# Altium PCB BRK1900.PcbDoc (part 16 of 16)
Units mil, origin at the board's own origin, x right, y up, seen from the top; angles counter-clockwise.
Board outline 8858.27 x 5905.51 mil, 10 copper layers (L1-TOP, L2-GND, L3-PWR, L4-GND, L5-PWR, L6-PWR, L7-GND, L8-SIG, L9-GND, L10-BOT), stack 48.824 mil thick; 456 components, 571 nets, 2296 pads, 2416 vias.
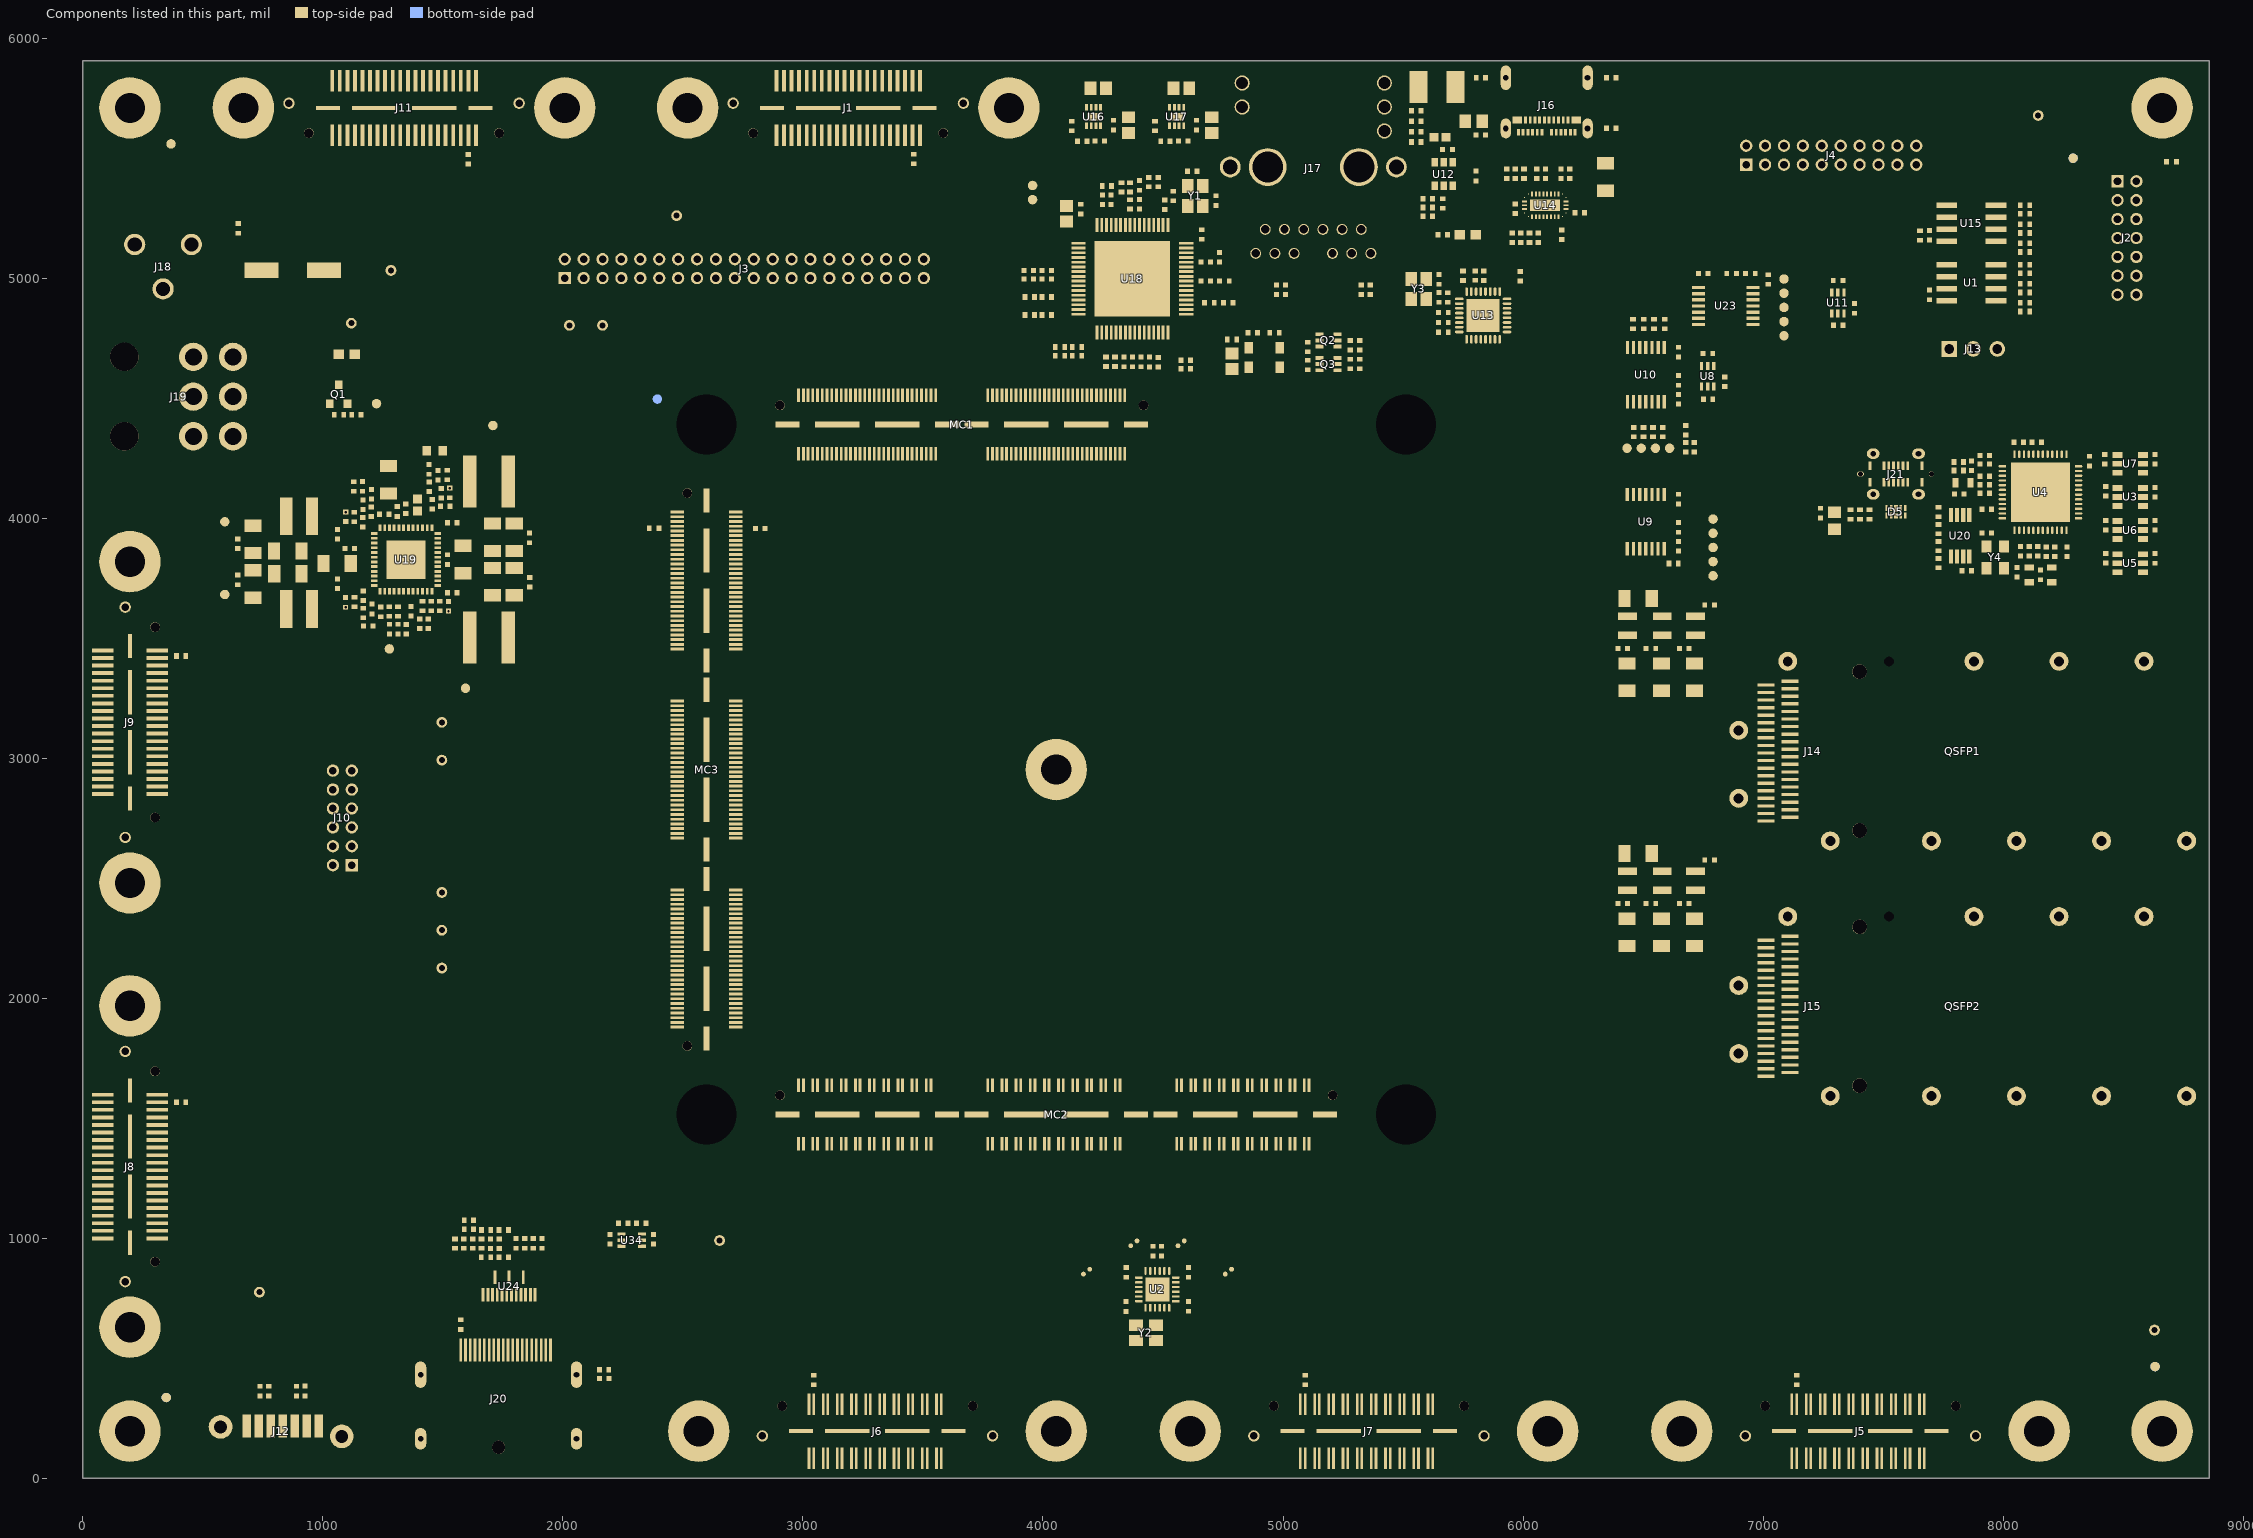
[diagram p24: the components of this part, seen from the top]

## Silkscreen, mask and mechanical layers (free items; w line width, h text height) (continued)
Drill Drawing:
  drawing of 162 lines, arcs and shapes, not listed
  text "DRILL TABLE" at 9511.81,5524.57 h50
  text "Symbol" at 9550.58,5424.22 h47.91
  text "Count" at 9897.89,5424.22 h47.91
  text "Finished Hole Size" at 10343.61,5424.22 h47.91
  text "Slot Length" at 11249.66,5424.22 h47.91
  text "Plated" at 11988.06,5424.22 h47.91
  text "Drill Layer Pair" at 12335.37,5424.22 h47.91
  text "Via/Pad" at 13137.65,5424.22 h47.91
  text "Hole Tolerance (+)" at 13540.83,5424.22 h47.91
  text "Hole Tolerance (-)" at 14438.89,5424.22 h47.91
  text "2420" at 9897.89,5324.41 h39.92
  text "10.00mil (0.254mm)" at 10343.61,5324.41 h39.92
  text "-" at 11249.66,5324.41 h39.92
  text "PTH" at 11988.06,5324.41 h39.92
  text "L1-TOP - L10-BOT" at 12335.37,5324.41 h39.92
  text "(Mixed)" at 13137.65,5324.41 h39.92
  text "3.00mil (0.076mm)" at 13540.83,5324.41 h39.92
  text "3.00mil (0.076mm)" at 14438.89,5324.41 h39.92
  text "1" at 9897.89,5224.6 h39.92
  text "20.47mil (0.520mm)" at 10343.61,5224.6 h39.92
  text "-" at 11249.66,5224.6 h39.92
  text "NPTH" at 11988.06,5224.6 h39.92
  text "L1-TOP - L10-BOT" at 12335.37,5224.6 h39.92
  text "Pad" at 13137.65,5224.6 h39.92
  text "3.00mil (0.076mm)" at 13540.83,5224.6 h39.92
  text "3.00mil (0.076mm)" at 14438.89,5224.6 h39.92
  text "E" at 9528.92,5214.61 h44.36
  text "1" at 9897.89,5124.8 h39.92
  text "20.47mil (0.520mm)" at 10343.61,5124.8 h39.92
  text "28.35mil (0.720mm)" at 11249.66,5124.8 h39.92
  text "NPTH" at 11988.06,5124.8 h39.92
  text "L1-TOP - L10-BOT" at 12335.37,5124.8 h39.92
  text "Pad" at 13137.65,5124.8 h39.92
  text "3.00mil (0.076mm)" at 13540.83,5124.8 h39.92
  text "3.00mil (0.076mm)" at 14438.89,5124.8 h39.92
  text "H" at 9528.92,5114.8 h44.36
  text "4" at 9897.89,5024.99 h39.92
  text "23.62mil (0.600mm)" at 10343.61,5024.99 h39.92
  text "33.47mil (0.850mm)" at 11249.66,5024.99 h39.92
  text "PTH" at 11988.06,5024.99 h39.92
  text "L1-TOP - L10-BOT" at 12335.37,5024.99 h39.92
  text "Pad" at 13137.65,5024.99 h39.92
  text "3.00mil (0.076mm)" at 13540.83,5024.99 h39.92
  text "3.00mil (0.076mm)" at 14438.89,5024.99 h39.92
  text "G" at 9528.92,5015 h44.36
  text "2" at 9897.89,4925.18 h39.92
  text "23.62mil (0.600mm)" at 10343.61,4925.18 h39.92
  text "62.99mil (1.600mm)" at 11249.66,4925.18 h39.92
  text "PTH" at 11988.06,4925.18 h39.92
  text "L1-TOP - L10-BOT" at 12335.37,4925.18 h39.92
  text "Pad" at 13137.65,4925.18 h39.92
  text "3.00mil (0.076mm)" at 13540.83,4925.18 h39.92
  text "3.00mil (0.076mm)" at 14438.89,4925.18 h39.92
  text "2" at 9897.89,4825.37 h39.92
  text "23.62mil (0.600mm)" at 10343.61,4825.37 h39.92
  text "66.93mil (1.700mm)" at 11249.66,4825.37 h39.92
  text "PTH" at 11988.06,4825.37 h39.92
  text "L1-TOP - L10-BOT" at 12335.37,4825.37 h39.92
  text "Pad" at 13137.65,4825.37 h39.92
  text "3.00mil (0.076mm)" at 13540.83,4825.37 h39.92
  text "3.00mil (0.076mm)" at 14438.89,4825.37 h39.92
  text "2" at 9897.89,4725.57 h39.92
  text "23.62mil (0.600mm)" at 10343.61,4725.57 h39.92
  text "82.68mil (2.100mm)" at 11249.66,4725.57 h39.92
  text "PTH" at 11988.06,4725.57 h39.92
  text "L1-TOP - L10-BOT" at 12335.37,4725.57 h39.92
  text "Pad" at 13137.65,4725.57 h39.92
  text "3.00mil (0.076mm)" at 13540.83,4725.57 h39.92
  text "3.00mil (0.076mm)" at 14438.89,4725.57 h39.92
  text "2" at 9897.89,4625.76 h39.92
  text "23.62mil (0.600mm)" at 10343.61,4625.76 h39.92
  text "86.61mil (2.200mm)" at 11249.66,4625.76 h39.92
  text "PTH" at 11988.06,4625.76 h39.92
  text "L1-TOP - L10-BOT" at 12335.37,4625.76 h39.92
  text "Pad" at 13137.65,4625.76 h39.92
  text "3.00mil (0.076mm)" at 13540.83,4625.76 h39.92
  text "3.00mil (0.076mm)" at 14438.89,4625.76 h39.92
  text "14" at 9897.89,4525.95 h39.92
  text "25.00mil (0.635mm)" at 10343.61,4525.95 h39.92
  text "-" at 11249.66,4525.95 h39.92
  text "PTH" at 11988.06,4525.95 h39.92
  text "L1-TOP - L10-BOT" at 12335.37,4525.95 h39.92
  text "Pad" at 13137.65,4525.95 h39.92
  text "3.00mil (0.076mm)" at 13540.83,4525.95 h39.92
  text "3.00mil (0.076mm)" at 14438.89,4525.95 h39.92
  text "14" at 9897.89,4426.15 h39.92
  text "31.50mil (0.800mm)" at 10343.61,4426.15 h39.92
  text "-" at 11249.66,4426.15 h39.92
  text "PTH" at 11988.06,4426.15 h39.92
  text "L1-TOP - L10-BOT" at 12335.37,4426.15 h39.92
  text "Pad" at 13137.65,4426.15 h39.92
  text "3.00mil (0.076mm)" at 13540.83,4426.15 h39.92
  text "3.00mil (0.076mm)" at 14438.89,4426.15 h39.92
  text "86" at 9897.89,4326.34 h39.92
  text "31.50mil (0.800mm)" at 10343.61,4326.34 h39.92
  text "-" at 11249.66,4326.34 h39.92
  text "PTH" at 11988.06,4326.34 h39.92
  text "L1-TOP - L10-BOT" at 12335.37,4326.34 h39.92
  text "Pad" at 13137.65,4326.34 h39.92
  text "3.15mil (0.080mm)" at 13540.83,4326.34 h39.92
  text "3.15mil (0.080mm)" at 14438.89,4326.34 h39.92
  text "C" at 9528.92,4316.35 h44.36
  text "12" at 9897.89,4226.53 h39.92
  text "35.04mil (0.890mm)" at 10343.61,4226.53 h39.92
  text "-" at 11249.66,4226.53 h39.92
  text "PTH" at 11988.06,4226.53 h39.92
  text "L1-TOP - L10-BOT" at 12335.37,4226.53 h39.92
  text "Pad" at 13137.65,4226.53 h39.92
  text "5.00mil (0.127mm)" at 13540.83,4226.53 h39.92
  text "0.00mil (0.000mm)" at 14438.89,4226.53 h39.92
  text "A" at 9528.92,4216.54 h44.36
  text "3" at 9897.89,4126.73 h39.92
  text "40.00mil (1.016mm)" at 10343.61,4126.73 h39.92
  text "-" at 11249.66,4126.73 h39.92
  text "PTH" at 11988.06,4126.73 h39.92
  text "L1-TOP - L10-BOT" at 12335.37,4126.73 h39.92
  text "Pad" at 13137.65,4126.73 h39.92
  text "3.00mil (0.076mm)" at 13540.83,4126.73 h39.92
  text "3.00mil (0.076mm)" at 14438.89,4126.73 h39.92
  text "20" at 9897.89,4026.92 h39.92
  text "40.16mil (1.020mm)" at 10343.61,4026.92 h39.92
  text "-" at 11249.66,4026.92 h39.92
  text "NPTH" at 11988.06,4026.92 h39.92
  text "L1-TOP - L10-BOT" at 12335.37,4026.92 h39.92
  text "Pad" at 13137.65,4026.92 h39.92
  text "3.00mil (0.076mm)" at 13540.83,4026.92 h39.92
  text "3.00mil (0.076mm)" at 14438.89,4026.92 h39.92
  text "2" at 9897.89,3927.11 h39.92
  text "41.34mil (1.050mm)" at 10343.61,3927.11 h39.92
  text "-" at 11249.66,3927.11 h39.92
  text "NPTH" at 11988.06,3927.11 h39.92
  text "L1-TOP - L10-BOT" at 12335.37,3927.11 h39.92
  text "Pad" at 13137.65,3927.11 h39.92
  text "3.00mil (0.076mm)" at 13540.83,3927.11 h39.92
  text "3.00mil (0.076mm)" at 14438.89,3927.11 h39.92
  text "J" at 9528.92,3917.12 h44.36
  text "22" at 9897.89,3827.3 h39.92
  text "41.34mil (1.050mm)" at 10343.61,3827.3 h39.92
  text "-" at 11249.66,3827.3 h39.92
  text "PTH" at 11988.06,3827.3 h39.92
  text "L1-TOP - L10-BOT" at 12335.37,3827.3 h39.92
  text "Pad" at 13137.65,3827.3 h39.92
  text "3.00mil (0.076mm)" at 13540.83,3827.3 h39.92
  text "3.00mil (0.076mm)" at 14438.89,3827.3 h39.92
  text "M" at 9528.92,3817.31 h44.36
  text "5" at 9897.89,3727.5 h39.92
  text "50.00mil (1.270mm)" at 10343.61,3727.5 h39.92
  text "-" at 11249.66,3727.5 h39.92
  text "PTH" at 11988.06,3727.5 h39.92
  text "L1-TOP - L10-BOT" at 12335.37,3727.5 h39.92
  text "Pad" at 13137.65,3727.5 h39.92
  text "4.00mil (0.102mm)" at 13540.83,3727.5 h39.92
  text "4.00mil (0.102mm)" at 14438.89,3727.5 h39.92
  text "N" at 9528.92,3717.5 h44.36
  text "2" at 9897.89,3627.69 h39.92
  text "53.15mil (1.350mm)" at 10343.61,3627.69 h39.92
  text "-" at 11249.66,3627.69 h39.92
  text "PTH" at 11988.06,3627.69 h39.92
  text "L1-TOP - L10-BOT" at 12335.37,3627.69 h39.92
  text "Pad" at 13137.65,3627.69 h39.92
  text "3.00mil (0.076mm)" at 13540.83,3627.69 h39.92
  text "3.00mil (0.076mm)" at 14438.89,3627.69 h39.92
  text "B" at 9528.92,3617.7 h44.36
  text "1" at 9897.89,3527.88 h39.92
  text "55.12mil (1.400mm)" at 10343.61,3527.88 h39.92
  text "-" at 11249.66,3527.88 h39.92
  text "NPTH" at 11988.06,3527.88 h39.92
  text "L1-TOP - L10-BOT" at 12335.37,3527.88 h39.92
  text "Pad" at 13137.65,3527.88 h39.92
  text "3.00mil (0.076mm)" at 13540.83,3527.88 h39.92
  text "3.00mil (0.076mm)" at 14438.89,3527.88 h39.92
  text "3" at 9897.89,3428.08 h39.92
  text "59.06mil (1.500mm)" at 10343.61,3428.08 h39.92
  text "-" at 11249.66,3428.08 h39.92
  text "PTH" at 11988.06,3428.08 h39.92
  text "L1-TOP - L10-BOT" at 12335.37,3428.08 h39.92
  text "Pad" at 13137.65,3428.08 h39.92
  text "3.00mil (0.076mm)" at 13540.83,3428.08 h39.92
  text "3.00mil (0.076mm)" at 14438.89,3428.08 h39.92
  text "4" at 9897.89,3328.27 h39.92
  text "61.02mil (1.550mm)" at 10343.61,3328.27 h39.92
  text "-" at 11249.66,3328.27 h39.92
  text "NPTH" at 11988.06,3328.27 h39.92
  text "L1-TOP - L10-BOT" at 12335.37,3328.27 h39.92
  text "Pad" at 13137.65,3328.27 h39.92
  text "3.00mil (0.076mm)" at 13540.83,3328.27 h39.92
  text "3.00mil (0.076mm)" at 14438.89,3328.27 h39.92
  text "D" at 9528.92,3318.28 h44.36
  text "2" at 9897.89,3228.46 h39.92
  text "62.00mil (1.575mm)" at 10343.61,3228.46 h39.92
  text "-" at 11249.66,3228.46 h39.92
  text "PTH" at 11988.06,3228.46 h39.92
  text "L1-TOP - L10-BOT" at 12335.37,3228.46 h39.92
  text "Pad" at 13137.65,3228.46 h39.92
  text "4.00mil (0.102mm)" at 13540.83,3228.46 h39.92
  text "4.00mil (0.102mm)" at 14438.89,3228.46 h39.92
  text "6" at 9897.89,3128.65 h39.92
  text "70.87mil (1.800mm)" at 10343.61,3128.65 h39.92
  text "-" at 11249.66,3128.65 h39.92
  text "PTH" at 11988.06,3128.65 h39.92
  text "L1-TOP - L10-BOT" at 12335.37,3128.65 h39.92
  text "Pad" at 13137.65,3128.65 h39.92
  text "3.00mil (0.076mm)" at 13540.83,3128.65 h39.92
  text "3.00mil (0.076mm)" at 14438.89,3128.65 h39.92
  text "2" at 9897.89,3028.85 h39.92
  text "118.11mil (3.000mm)" at 10343.61,3028.85 h39.92
  text "-" at 11249.66,3028.85 h39.92
  text "NPTH" at 11988.06,3028.85 h39.92
  text "L1-TOP - L10-BOT" at 12335.37,3028.85 h39.92
  text "Pad" at 13137.65,3028.85 h39.92
  text "3.00mil (0.076mm)" at 13540.83,3028.85 h39.92
  text "3.00mil (0.076mm)" at 14438.89,3028.85 h39.92
  text "F" at 9528.92,3018.85 h44.36
  text "19" at 9897.89,2929.04 h39.92
  text "125.98mil (3.200mm)" at 10343.61,2929.04 h39.92
  text "-" at 11249.66,2929.04 h39.92
  text "PTH" at 11988.06,2929.04 h39.92
  text "L1-TOP - L10-BOT" at 12335.37,2929.04 h39.92
  text "Pad" at 13137.65,2929.04 h39.92
  text "3.00mil (0.076mm)" at 13540.83,2929.04 h39.92
  text "3.00mil (0.076mm)" at 14438.89,2929.04 h39.92
  text "O" at 9528.92,2919.05 h44.36
  text "2" at 9897.89,2829.23 h39.92
  text "128.00mil (3.251mm)" at 10343.61,2829.23 h39.92
  text "-" at 11249.66,2829.23 h39.92
  text "PTH" at 11988.06,2829.23 h39.92
  text "L1-TOP - L10-BOT" at 12335.37,2829.23 h39.92
  text "Pad" at 13137.65,2829.23 h39.92
  text "4.00mil (0.102mm)" at 13540.83,2829.23 h39.92
  text "4.00mil (0.102mm)" at 14438.89,2829.23 h39.92
  text "4" at 9897.89,2729.43 h39.92
  text "250.00mil (6.350mm)" at 10343.61,2729.43 h39.92
  text "-" at 11249.66,2729.43 h39.92
  text "NPTH" at 11988.06,2729.43 h39.92
  text "L1-TOP - L10-BOT" at 12335.37,2729.43 h39.92
  text "Pad" at 13137.65,2729.43 h39.92
  text "3.00mil (0.076mm)" at 13540.83,2729.43 h39.92
  text "3.00mil (0.076mm)" at 14438.89,2729.43 h39.92
  text "I" at 9536.31,2719.43 h44.36
  text "2657 Total" at 9897.89,2629.62 h39.92
  text "Slot definitions :" at 9550.58,2526.46 h39.92
  text "Routed Path Length" at 10247.08,2526.46 h39.92
  text "= Calculated from tool start centre position to tool end centre position." at 10990.14,2526.46 h39.92
  text "Slot Length" at 10247.08,2453.25 h39.92
  text "= Routed Path Length + Tool Size = Slot length as defined in the PCB layout" at 10710.77,2453.25 h39.92
Doc-Assy-Top:
  lines w4.9: 6455.41,-1165.11 6455.41,-465.69 9394.83,-465.69 ; 6455.41,-929.08 9394.83,-929.08 ; 6899,-1165.11 6899,-929.08 ; 7587.2,-1165.11 7587.2,-929.08 ; 7724.8,-928.79 7724.8,-465.69 ; 8604.56,-1165.11 8604.56,-929.08
  lines w4.91: -809.63,527.32 -613.38,527.32 ; -809.63,2612.53 -613.38,2612.53 ; -809.63,4697.75 -613.38,4697.75 ; 1692.62,-1361.63 1692.62,-1165.38 ; 1692.62,6390.45 1692.62,6586.7 ; 4391.13,-1361.63 4391.13,-1165.38 ; 4391.13,6390.45 4391.13,6586.7 ; 5176.15,-1361.63 9591.89,-1361.63 ; 7089.64,-1361.63 7089.64,-1165.38 ; 7089.64,6390.45 7089.64,6586.7 ; 9395.64,527.32 9591.89,527.32 ; 9395.64,2612.53 9591.89,2612.53 ; 9395.64,4697.75 9591.89,4697.75 ; 9591.89,-1361.63 9591.89,6586.7 -809.63,6586.7 -809.63,-1361.63 9591.89,-1361.63 ; -613.38,-1165.38 -613.38,6390.45 9395.64,6390.45 9395.64,-1165.38 -613.38,-1165.38
  text "1" at 320.15,6457.32 h68.69
  text "2" at 3019.31,6457.32 h68.69
  text "3" at 5712.91,6457.32 h68.69
  text "4" at 8412.41,6457.32 h68.69
  text "A" at -739.13,5651.55 h68.69
  text "A" at 9472.33,5651.55 h68.69
  text "B" at -739.13,3566.34 h68.69
  text "B" at 9472.33,3566.34 h68.69
  text "C" at -739.13,1481.12 h68.69
  text "C" at 9472.33,1481.12 h68.69
  text "TITLE:" at 6531.58,-542.92 h44.14
  text "Opal Kelly" at 7802.04,-573.82 h68.66
  text "D" at -739.13,-599.18 h68.69
  text "D" at 9472.33,-599.18 h68.69
  text "13500 SW 72nd Ave Suite 100" at 7802.04,-689.66 h68.66
  text "Portland, OR 97223" at 7802.04,-786.2 h68.66
  text "'.Part_Number' / Assembly Drawing" at 6563.33,-787.86 h68.66
  text "www.opalkelly.com" at 7802.04,-882.74 h68.66
  text "(Top)" at 6563.33,-899.67 h68.66
  text "REV:" at 6510.01,-994.48 h44.14
  text "SIZE:" at 6958.84,-994.48 h44.14
  text "ENGINEER:" at 7647.05,-994.48 h44.14
  text "DATE:" at 8664.4,-994.48 h44.14
  text "'.PCB_Revision'XX" at 6569.85,-1114.17 h68.66
  text "ANSI A" at 7018.68,-1114.17 h68.66
  text "RCA" at 7706.89,-1114.17 h68.66
  text ".PRINT_DATE" at 8724.24,-1114.17 h68.66
  text "1" at 320.15,-1300.94 h68.69
  text "2" at 3019.31,-1300.94 h68.69
  text "3" at 5712.91,-1300.94 h68.69
  text "4" at 8412.41,-1300.94 h68.69
Doc-Assy-Bot:
  lines w4.9: -611.4,-929.36 2327.29,-929.36 ; -611.4,-466.09 2327.29,-466.09 2327.29,-1165.33 ; 178.68,-1165.33 178.68,-929.36 ; 1058.21,-929.06 1058.21,-466.09 ; 1195.78,-1165.33 1195.78,-929.36 ; 1883.82,-1165.33 1883.82,-929.36
  lines w4.91: -808.42,526.69 -612.21,526.69 ; -808.42,2611.39 -612.21,2611.39 ; -808.42,4696.08 -612.21,4696.08 ; 1693.22,-1361.8 1693.22,-1165.6 ; 1693.22,6388.37 1693.22,6584.58 ; 3606.24,-1361.8 -808.42,-1361.8 ; 4391.07,-1361.8 4391.07,-1165.6 ; 4391.07,6388.37 4391.07,6584.58 ; 7088.91,-1361.8 7088.91,-1165.6 ; 7088.91,6388.37 7088.91,6584.58 ; 9394.34,526.69 9590.55,526.69 ; 9394.34,2611.39 9590.55,2611.39 ; 9394.34,4696.08 9590.55,4696.08 ; -808.42,-1361.8 9590.55,-1361.8 9590.55,6584.58 -808.42,6584.58 -808.42,-1361.8 ; -612.21,-1165.6 9394.34,-1165.6 9394.34,6388.37 -612.21,6388.37 -612.21,-1165.6
  text "4" at 370.77,6455.23 h68.67
  text "3" at 3069.61,6455.23 h68.67
  text "2" at 5762.55,6455.23 h68.67
  text "1" at 8461.05,6455.23 h68.67
  text "A" at -688.88,5649.65 h68.67
  text "A" at 9520.06,5649.65 h68.67
  text "B" at -688.88,3564.95 h68.67
  text "B" at 9520.06,3564.95 h68.67
  text "C" at -688.88,1480.25 h68.67
  text "C" at 9520.06,1480.25 h68.67
  text "TITLE:" at 2251.14,-543.3 h44.13
  text "Opal Kelly" at 981,-574.18 h68.64
  text "D" at -688.88,-599.54 h68.67
  text "D" at 9520.06,-599.54 h68.67
  text "13500 SW 72nd Ave Suite 100" at 981,-690 h68.64
  text "Portland, OR 97223" at 981,-786.52 h68.64
  text "'.Part_Number' / Assembly Drawing" at 2219.4,-788.17 h68.64
  text "www.opalkelly.com" at 981,-883.03 h68.64
  text "(Bottom)" at 2219.4,-899.96 h68.64
  text "DATE:" at 118.85,-994.74 h44.13
  text "ENGINEER:" at 1135.95,-994.74 h44.13
  text "SIZE:" at 1823.99,-994.74 h44.13
  text "REV:" at 2272.71,-994.74 h44.13
  text ".PRINT_DATE" at 59.02,-1114.4 h68.64
  text "RCA" at 1076.12,-1114.4 h68.64
  text "ANSI A" at 1764.16,-1114.4 h68.64
  text "'.PCB_Revision'XX" at 2212.88,-1114.4 h68.64
  text "4" at 370.77,-1301.13 h68.67
  text "3" at 3069.61,-1301.13 h68.67
  text "2" at 5762.55,-1301.13 h68.67
  text "1" at 8461.05,-1301.13 h68.67
Doc-Fab:
  lines w5: 10935.28,-537.72 10935.28,518.43 15474.46,518.43 ; 10935.28,108.43 12695.28,108.43 ; 10935.28,328.43 12695.28,328.43 ; 10935.28,438.43 12695.28,438.43 ; 11355.28,-537.72 11355.28,518.43 ; 12695.28,-537.72 12695.28,518.43 ; 12695.28,-341.57 15475.28,-341.57 ; 12695.28,98.43 15474.46,98.43 ; 13255.28,-537.72 13255.28,-341.57 ; 13935.28,-341.57 13935.28,98.43 ; 14585.28,-537.72 14585.28,-341.57
  lines w5.49: -788.55,1850.61 -568.77,1850.61 ; -788.55,4460.55 -568.77,4460.55 ; -788.55,7070.49 -568.77,7070.49 ; 1958.75,-759.33 1958.75,-539.55 ; 1958.75,9460.64 1958.75,9680.43 ; 4706.06,-759.33 4706.06,-539.55 ; 4706.06,9460.64 4706.06,9680.43 ; 7453.36,-759.33 7453.36,-539.55 ; 7453.36,9460.64 7453.36,9680.43 ; 10200.67,-759.33 10200.67,-539.55 ; 10200.67,9460.64 10200.67,9680.43 ; 12947.97,-759.33 12947.97,-539.55 ; 12947.97,9460.64 12947.97,9680.43 ; 15475.49,1850.61 15695.28,1850.61 ; 15475.49,4460.55 15695.28,4460.55 ; 15475.49,7070.49 15695.28,7070.49 ; -788.55,-759.33 -788.55,9680.43 15695.28,9680.43 15695.28,-759.33 -788.55,-759.33 ; -568.77,-539.55 -568.77,9460.64 15475.49,9460.64 15475.49,-539.55 -568.77,-539.55
  text "1" at 564.59,9537.57 h76.92
  text "2" at 3307.13,9537.57 h76.92
  text "3" at 6042.72,9537.57 h76.92
  text "4" at 8797.35,9537.57 h76.92
  text "5" at 11543.55,9537.57 h76.92
  text "6" at 14296.35,9537.57 h76.92
  text "A" at -706.14,8281.5 h76.92
  text "A" at 15557.91,8281.5 h76.92
  text "B" at -706.14,5666.06 h76.92
  text "B" at 15557.91,5666.06 h76.92
  text "C" at -706.14,3056.12 h76.92
  text "C" at 15557.91,3056.12 h76.92
  text "REVISION:" at 10964.28,458.43 h40
  text "DESCRIPTION:" at 11394.28,458.43 h40
  text "D" at -706.14,451.68 h76.92
  text "D" at 15557.91,451.68 h76.92
  text "PART NUMBER:" at 12775.28,378.43 h75
  text "AXX" at 10965.28,358.43 h50
  text "Initial Release" at 11395.28,358.43 h50
  text "BXX" at 10965.28,248.43 h50
  text "QSFP, DP, Clock, Enpirion, SATA," at 11395.28,248.43 h50
  text "SZG Mounting updates." at 11394.98,147.24 h50
  text "'.Part_Number'-PCB-'.PCB_Revision'XX" at 12795.28,98.43 h130
  text "TITLE:" at 12755.28,18.43 h40
  text "Opal Kelly" at 13995.28,-1.57 h60
  text "13500 SW 72nd Ave Suite 100" at 13995.28,-101.57 h60
  text "Portland, OR 97223" at 13995.28,-201.57 h60
  text "'.Part_Number' / Fabrication Drawing" at 12795.28,-281.57 h60
  text "www.opalkelly.com" at 13995.28,-301.57 h60
  text "SIZE:" at 12755.28,-401.57 h40
  text "ENGINEER:" at 13315.28,-401.57 h40
  text "DATE:" at 14635.28,-401.57 h40
  text "ANSI A" at 12795.28,-501.57 h60
  text "RCA" at 13355.28,-501.57 h60
  text ".PRINT_DATE" at 14675.28,-501.57 h60
  text "1" at 564.59,-682.41 h76.92
  text "2" at 3307.13,-682.41 h76.92
  text "3" at 6042.72,-682.41 h76.92
  text "4" at 8797.35,-682.41 h76.92
  text "5" at 11543.55,-682.41 h76.92
  text "6" at 14296.35,-682.41 h76.92

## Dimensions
0,0 to 8858.27,0 on Dimensions
0,0 to 0,5905.51 on Dimensions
